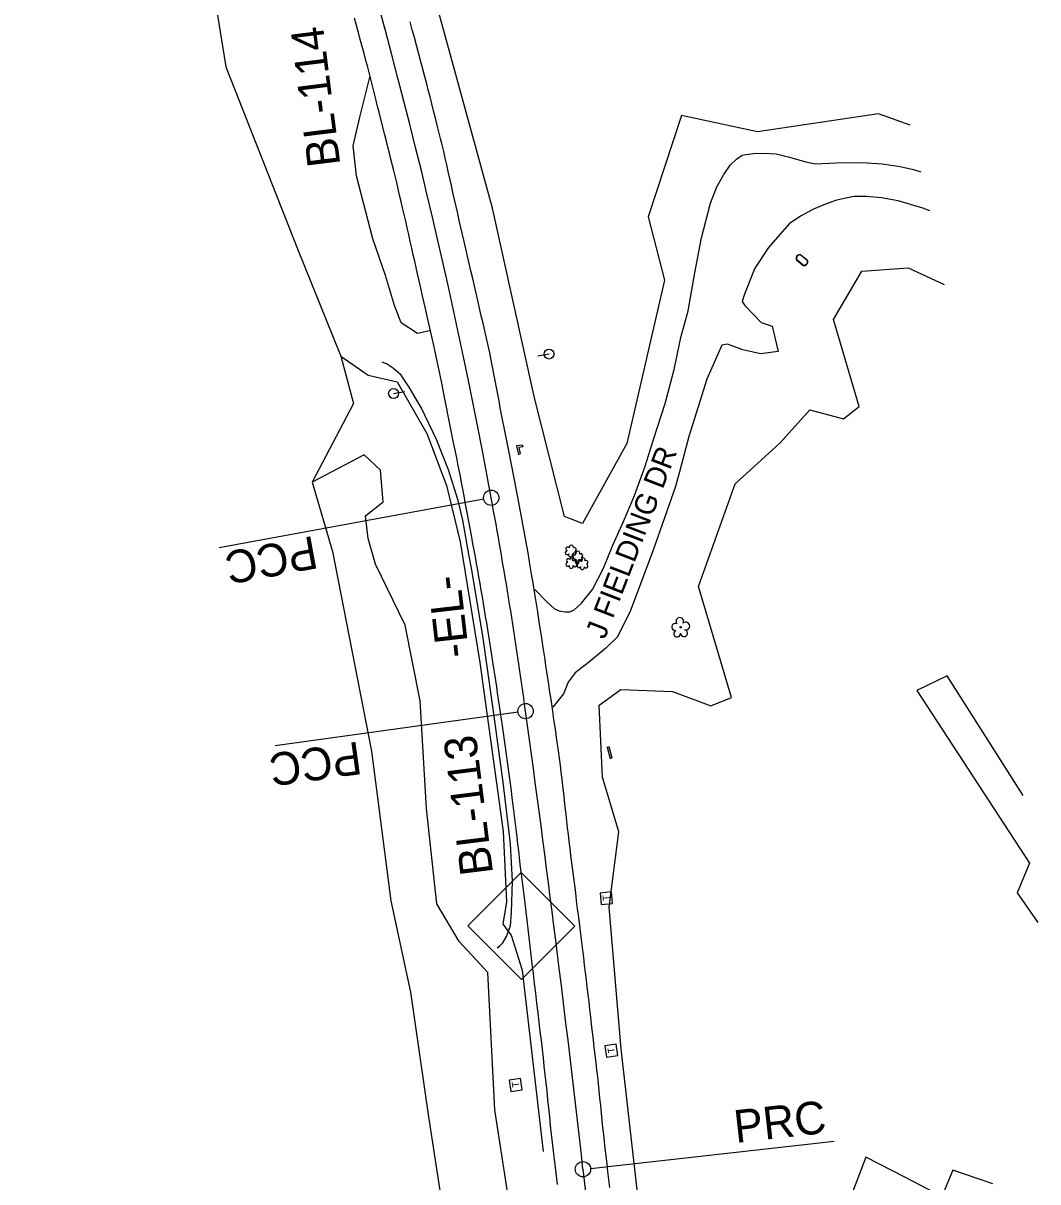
# Model space of a CAD drawing. Extents: x 476627 to 479509, y 495837 to 499842.
# Drawn here: x 477748 to 478245, y 498393 to 498961 of the extents above; entities that cross this region are included whole.
import ezdxf

# ---------------------------------------------------------------- set-up
doc = ezdxf.new("R2010")
doc.units = 0
for name, color, linetype in [('CTL Secondary Horizontal and Vertical CELL', 7, 'Continuous'), ('CTL Secondary Horizontal and Vertical Text', 7, 'Continuous'), ('Exist Guardrail', 7, 'Continuous'), ('Exist Horizontal Alignment', 7, 'Continuous'), ('Exist Horizontal Alignment Direction Label', 7, 'Continuous'), ('Exist Roads EOP', 7, 'Continuous'), ('Exist Roads Soil', 7, 'Continuous'), ('Exist Roads Soil Text', 7, 'Continuous'), ('Exist Structure Minor Head and End Wall', 7, 'Continuous'), ('Exist Utilities Power Pole CELL', 7, 'Continuous'), ('Exist Utilities Telephone Pedestal CELL', 7, 'Continuous'), ('Exist Utilities Water Meter CELL', 7, 'Continuous'), ('Exist Vegetation Hedge Row', 7, 'Continuous'), ('Exist Vegetation Shrub CELL', 7, 'Continuous'), ('Exist Vegetation Tree CELL', 7, 'Continuous'), ('Exist Vegetation Woods Line', 7, 'Continuous')]:
    doc.layers.add(name, color=color, linetype=linetype)

msp = doc.modelspace()

# ---------------------------------------------------------------- linework, layer by layer
at = {"layer": 'CTL Secondary Horizontal and Vertical CELL'}
msp.add_line((477991.73, 498518.4), (477991.73, 498518.4), dxfattribs=at)
msp.add_lwpolyline([(477965.66, 498518.49), (477991.87, 498544.7), (478018.12, 498518.44), (477991.91, 498492.24)], close=True, dxfattribs=at)
at = {"layer": 'Exist Guardrail'}
for points in [[(477966.35, 498699.59), (477963.2, 498717.17), (477960.96, 498726.82), (477956.29, 498741.9), (477950.37, 498756.69), (477942.99, 498772.06), (477937.02, 498782.44), (477933.02, 498788.21), (477929.33, 498791.5), (477925.8, 498793.82), (477923.73, 498794.65)], [(477980.13, 498507.83), (477981.43, 498508.73), (477982.83, 498510.24), (477984.67, 498513.24), (477986.54, 498518.59), (477987.15, 498525.08), (477987.62, 498540.38), (477986.53, 498558.71), (477982.99, 498588.89), (477977.95, 498625.97), (477973.03, 498660.6), (477967.5, 498693.64), (477966.35, 498699.59)]]:
    msp.add_lwpolyline(points, dxfattribs=at)
at = {"layer": 'Exist Horizontal Alignment'}
for p, q in [((477973.47, 498727.54), (477843.87, 498703.69)), ((477990.28, 498623.17), (477871.38, 498606.73)), ((478025.82, 498399.73), (478145.11, 498413.12))]:
    msp.add_line(p, q, dxfattribs=at)
for centre in [(477977.16, 498728.22), (477994, 498623.69), (478022.1, 498399.31)]:
    msp.add_circle(centre, 3.75, dxfattribs=at)
for centre, radius, start, end in [((475150.42, 498208.04), 2874.21, 10.42705, 25.34825), ((475642.7, 498298.63), 2373.66, 7.87106, 10.42705), ((469239.4, 497413.39), 8837.86, 6.405023, 7.871057), ((592937.27, 511299.31), 115636.96, 186.405023, 186.7177067)]:
    msp.add_arc(centre, radius, start, end, dxfattribs=at)
at = {"layer": 'Exist Roads EOP'}
for points in [[(478009.56, 498391.82), (478009.06, 498396.03), (478008.58, 498400.16), (478008.1, 498404.2), (478007.63, 498408.24), (478007.17, 498412.34), (478006.71, 498416.51), (478006.26, 498420.74), (478005.81, 498424.99), (478005.37, 498429.2), (478004.93, 498433.37), (478004.49, 498437.5), (478004.05, 498441.61), (478003.6, 498445.73), (478003.15, 498449.84), (478002.69, 498453.96), (478002.21, 498458.14), (478001.71, 498462.44), (478001.2, 498466.85), (478000.66, 498471.38), (478000.11, 498476), (477999.55, 498480.7), (477998.99, 498485.48), (477998.41, 498490.32), (477997.83, 498495.13), (477997.28, 498499.77), (477996.74, 498504.25), (477996.23, 498508.58), (477995.72, 498512.81), (477995.22, 498517.04), (477994.72, 498521.25), (477994.22, 498525.46), (477993.73, 498529.6), (477993.25, 498533.62), (477992.77, 498537.54), (477992.3, 498541.34), (477991.84, 498545.02), (477991.41, 498548.57), (477991.01, 498551.99), (477990.64, 498555.28), (477990.27, 498558.6), (477989.85, 498562.14), (477989.4, 498565.87), (477988.9, 498569.81), (477988.4, 498573.77), (477987.92, 498577.58), (477987.46, 498581.23), (477987.02, 498584.73), (477986.58, 498588.18), (477986.12, 498591.68), (477985.65, 498595.23), (477985.16, 498598.82), (477984.67, 498602.43), (477984.17, 498605.99), (477983.68, 498609.52), (477983.2, 498613.01), (477982.71, 498616.44), (477982.23, 498619.8), (477981.74, 498623.09), (477981.26, 498626.31), (477980.78, 498629.47), (477980.3, 498632.59), (477979.83, 498635.67), (477979.37, 498638.71), (477978.91, 498641.74), (477978.43, 498644.81), (477977.95, 498647.92), (477977.47, 498651.06), (477976.97, 498654.23), (477976.47, 498657.4), (477975.96, 498660.57), (477975.45, 498663.75), (477974.93, 498666.93), (477974.41, 498670.11), (477973.89, 498673.29), (477973.36, 498676.47), (477972.82, 498679.67), (477972.27, 498682.9), (477971.71, 498686.17), (477971.13, 498689.48), (477970.55, 498692.78), (477969.97, 498696.05), (477969.38, 498699.28), (477968.8, 498702.47), (477968.21, 498705.68), (477967.61, 498708.95), (477966.99, 498712.3), (477966.36, 498715.72), (477965.72, 498719.15), (477965.09, 498722.54), (477964.47, 498725.89), (477963.86, 498729.19), (477963.25, 498732.44), (477962.65, 498735.62), (477962.05, 498738.72), (477961.46, 498741.75), (477960.87, 498744.75), (477960.27, 498747.75), (477959.66, 498750.76), (477959.05, 498753.78), (477958.43, 498756.77), (477957.24, 498762.63), (477956.12, 498768.26), (477955.08, 498773.46), (477954.12, 498778.28), (477953.07, 498783.47), (477951.92, 498789.02), (477950.83, 498794.22), (477949.79, 498799.08), (477948.69, 498804.31), (477947.48, 498809.97), (477946.19, 498815.75), (477944.83, 498821.54), (477943.54, 498827.05), (477942.31, 498832.33), (477941.03, 498837.96), (477940.36, 498840.94), (477939.67, 498844.02), (477938.96, 498847.19), (477938.24, 498850.44), (477937.5, 498853.77), (477936.75, 498857.12), (477936.01, 498860.44), (477935.26, 498863.72), (477934.52, 498866.97), (477933.78, 498870.18), (477933.04, 498873.35), (477932.31, 498876.47), (477931.58, 498879.56), (477930.86, 498882.59), (477929.44, 498888.42), (477928.05, 498894.02), (477927.33, 498896.91), (477926.59, 498899.87), (477925.83, 498902.92), (477925.07, 498905.94), (477923.64, 498911.64), (477922.26, 498916.99), (477921.54, 498919.84), (477920.78, 498922.85), (477919.99, 498926.02), (477919.18, 498929.28), (477918.35, 498932.54), (477917.51, 498935.82), (477916.65, 498939.1), (477915.78, 498942.41), (477914.89, 498945.77), (477913.97, 498949.18), (477913.04, 498952.63), (477912.08, 498956.11), (477911.11, 498959.59), (477910.14, 498963.08)], [(478035.26, 498390.31), (478034.8, 498394.27), (478034.34, 498398.18), (478033.89, 498402.04), (478033.45, 498405.81), (478033.03, 498409.46), (478032.63, 498412.97), (478032.26, 498416.36), (478031.89, 498419.74), (478031.53, 498423.22), (478031.16, 498426.81), (478030.78, 498430.51), (478030.41, 498434.2), (478030.04, 498437.78), (478029.67, 498441.26), (478029.31, 498444.62), (478028.94, 498447.99), (478028.54, 498451.49), (478028.11, 498455.12), (478027.65, 498458.87), (478027.19, 498462.67), (478026.74, 498466.44), (478026.31, 498470.19), (478025.89, 498473.91), (478025.48, 498477.6), (478025.07, 498481.27), (478024.65, 498484.91), (478024.23, 498488.53), (478023.8, 498492.14), (478023.37, 498495.74), (478022.93, 498499.35), (478022.49, 498502.95), (478022.03, 498506.64), (478021.55, 498510.48), (478021.05, 498514.49), (478020.53, 498518.65), (478020, 498522.83), (478019.5, 498526.89), (478019.01, 498530.83), (478018.55, 498534.64), (478018.09, 498538.38), (478017.62, 498542.09), (478017.16, 498545.77), (478016.68, 498549.42), (478016.22, 498553.01), (478015.78, 498556.51), (478015.35, 498559.91), (478014.96, 498563.23), (478014.57, 498566.52), (478014.19, 498569.84), (478013.8, 498573.21), (478013.42, 498576.61), (478013.04, 498580.04), (478012.66, 498583.46), (478012.27, 498586.89), (478011.89, 498590.33), (478011.48, 498593.77), (478011.06, 498597.22), (478010.62, 498600.69), (478010.15, 498604.17), (478009.67, 498607.58), (478009.21, 498610.85), (478008.75, 498613.96), (478007.9, 498619.53), (478007.16, 498624.85), (478006.64, 498628.37), (478005.78, 498633.92), (478005.33, 498636.88), (478004.88, 498639.87), (478004.42, 498642.9), (478003.97, 498645.93), (478003.52, 498648.92), (478002.63, 498654.79), (478001.75, 498660.58), (478000.86, 498666.37), (477999.94, 498672.25), (477999.46, 498675.26), (477998.51, 498681.12), (477997.66, 498686.38), (477996.78, 498691.8), (477996.3, 498694.72), (477995.77, 498697.97), (477995.2, 498701.3), (477994.61, 498704.71), (477993.99, 498708.22), (477993.35, 498711.76), (477992.7, 498715.29), (477992.04, 498718.83), (477991.37, 498722.35), (477990.69, 498725.86), (477990.02, 498729.32), (477989.35, 498732.73), (477988.69, 498736.11), (477988.03, 498739.46), (477987.37, 498742.8), (477986.71, 498746.14), (477986.05, 498749.48), (477985.4, 498752.8), (477984.76, 498756.09), (477984.13, 498759.33), (477983.5, 498762.54), (477982.88, 498765.75), (477982.26, 498769), (477981.62, 498772.29), (477980.98, 498775.61), (477980.34, 498778.95), (477979.71, 498782.28), (477979.09, 498785.6), (477978.48, 498788.91), (477977.84, 498792.26), (477977.15, 498795.67), (477976.42, 498799.15), (477975.63, 498802.7), (477974.81, 498806.31), (477973.99, 498809.96), (477973.15, 498813.64), (477972.31, 498817.37), (477971.47, 498821.09), (477970.62, 498824.78), (477969.78, 498828.44), (477968.93, 498832.06), (477968.08, 498835.67), (477967.23, 498839.28), (477966.38, 498842.89), (477965.52, 498846.51), (477964.67, 498850.1), (477963.85, 498853.64), (477963.05, 498857.13), (477962.27, 498860.57), (477961.5, 498863.99), (477960.73, 498867.4), (477959.96, 498870.83), (477959.2, 498874.25), (477958.43, 498877.67), (477957.67, 498881.09), (477956.91, 498884.51), (477956.15, 498887.93), (477955.39, 498891.31), (477954.64, 498894.61), (477953.88, 498897.85), (477953.11, 498901.01), (477952.34, 498904.17), (477951.53, 498907.42), (477950.7, 498910.76), (477949.83, 498914.19), (477948.95, 498917.65), (477948.07, 498921.12), (477947.19, 498924.59), (477946.31, 498928.06), (477945.42, 498931.55), (477944.5, 498935.1), (477943.56, 498938.7), (477942.59, 498942.35), (477941.59, 498946.06), (477940.58, 498949.81), (477939.54, 498953.6), (477938.48, 498957.45), (477937.41, 498961.34)]]:
    msp.add_lwpolyline(points, dxfattribs=at)
at = {"layer": 'Exist Roads Soil'}
for points in [[(477946.96, 498810.01), (477940.97, 498808.62), (477933.11, 498813.85), (477929.86, 498822.29), (477925.33, 498837), (477919.23, 498854.95), (477911.11, 498885.89), (477909.62, 498900.51), (477912.88, 498914.64), (477917.69, 498934.2)], [(478041.97, 498716.51), (478047.32, 498729.34), (478052.49, 498743.63), (478056.64, 498756.73), (478062.4, 498774.32), (478066.75, 498790.95), (478070.01, 498806.62), (478073.56, 498819.77), (478076.93, 498838.36), (478080.08, 498855.54), (478084.56, 498872.46), (478087.7, 498880.52), (478091.07, 498886.6), (478094.12, 498891.05), (478097.25, 498894.05), (478100.09, 498895.97), (478101.9, 498896.41), (478105.6, 498896.8), (478110.38, 498896.94), (478116.74, 498896.61), (478122.68, 498895.17), (478131.22, 498892.78), (478135.86, 498891.84), (478146.28, 498892.29), (478158.83, 498892.47), (478168.6, 498891.75), (478177.52, 498890.43), (478184, 498889.01), (478187.63, 498887.9)], [(478192, 498868.68), (478188.62, 498869.98), (478176.51, 498873.68), (478168.31, 498875.11), (478160.97, 498875.8), (478154.98, 498875.68), (478150.03, 498874.79), (478145.8, 498873.88), (478140, 498871.6), (478134.77, 498869.38), (478128.71, 498866.06), (478123.16, 498862.38), (478113.02, 498850.7), (478106.2, 498840.61), (478101.18, 498827.95), (478100.11, 498824.41), (478101.42, 498822.29), (478105.39, 498818.19), (478109.32, 498814.08), (478114.84, 498812.2), (478117.63, 498799.76), (478109.13, 498798.68), (478100.46, 498800.61), (478092.87, 498803.38), (478090.11, 498802.9), (478082.8, 498786.24), (478073.98, 498758.22), (478069.43, 498740.96), (478067.38, 498733.66)], [(478067.38, 498733.66), (478056.64, 498702.95), (478045.19, 498672.47), (478038.91, 498659.85), (478033.38, 498654.47), (478024.69, 498647.29), (478018.26, 498642.42), (478014.87, 498637.95), (478012.54, 498632.09), (478007.31, 498625.71)], [(477998.52, 498683.24), (478004.16, 498677.45), (478008.15, 498673.88), (478010.51, 498672.75), (478013.43, 498672.33), (478015.47, 498672.29), (478017.7, 498673.09), (478021.46, 498676.53), (478026.72, 498683.29), (478032.08, 498693.73), (478036.74, 498704.92), (478041.97, 498716.51)]]:
    msp.add_lwpolyline(points, dxfattribs=at)
at = {"layer": 'Exist Structure Minor Head and End Wall'}
for p, q in [((477992.49, 498754.01), (477992.61, 498753.19)), ((477990.57, 498749.46), (477991.38, 498749.65)), ((478034.03, 498606.1), (478034.84, 498606.3)), ((478034.03, 498606.1), (478035.4, 498600.57)), ((478034.84, 498606.3), (478036.21, 498600.77)), ((478035.4, 498600.57), (478036.21, 498600.77))]:
    msp.add_line(p, q, dxfattribs=at)
for points in [[(477992.49, 498754.01), (477989.59, 498753.59), (477990.57, 498749.46)], [(477992.61, 498753.19), (477990.61, 498752.9), (477991.38, 498749.65)]]:
    msp.add_lwpolyline(points, dxfattribs=at)
at = {"layer": 'Exist Utilities Power Pole CELL'}
for p, q in [((478005.47, 498798.61), (477999.94, 498797.58)), ((478005.47, 498798.61), (478005.47, 498798.61)), ((477929.35, 498779.23), (477934.89, 498780.19)), ((477929.35, 498779.23), (477929.35, 498779.23))]:
    msp.add_line(p, q, dxfattribs=at)
for centre in [(478005.47, 498798.61), (477929.35, 498779.23)]:
    msp.add_circle(centre, 2.45, dxfattribs=at)
at = {"layer": 'Exist Utilities Telephone Pedestal CELL'}
for p, q in [((478033.49, 498531.98), (478033.49, 498531.98)), ((478036.03, 498457.28), (478036.03, 498457.28)), ((477989.1, 498440.53), (477989.1, 498440.53))]:
    msp.add_line(p, q, dxfattribs=at)
for points in [[(478036.57, 498529.54), (478036.03, 498535.11), (478030.46, 498534.57), (478031, 498529), (478036.57, 498529.54)], [(478039.22, 498455), (478038.4, 498460.53), (478032.86, 498459.71), (478033.69, 498454.17), (478039.22, 498455)], [(477992.26, 498438.21), (477991.52, 498443.75), (477985.97, 498443.01), (477986.71, 498437.47), (477992.26, 498438.21)]]:
    msp.add_lwpolyline(points, dxfattribs=at)
at = {"layer": 'Exist Utilities Water Meter CELL'}
msp.add_line((478129.35, 498844.62), (478129.35, 498844.62), dxfattribs=at)
for points in [[(478128.76, 498847.12), (478131.93, 498844.52)], [(478128.85, 498847.23), (478132.02, 498844.63)], [(478129.85, 498842.02), (478126.7, 498844.6)], [(478129.93, 498842.12), (478126.78, 498844.71)]]:
    msp.add_lwpolyline(points, dxfattribs=at)
for centre, radius, start, end in [((478128.35, 498845.44), 1.86, 74.3025, 206.9626), ((478128.34, 498845.45), 1.73, 75.7814, 205.527), ((478130.36, 498843.8), 1.86, 253.8322, 26.6336), ((478130.35, 498843.81), 1.73, 255.9551, 24.4366)]:
    msp.add_arc(centre, radius, start, end, dxfattribs=at)
at = {"layer": 'Exist Vegetation Hedge Row'}
for points in [[(477903.45, 498797.63), (477916.96, 498788.32), (477931.12, 498784.97), (477945.58, 498759.61), (477955.28, 498734.27), (477961.94, 498706.58)], [(477916.85, 498708.28), (477915.5, 498719.35), (477924.23, 498726.13), (477923, 498741.71), (477914.94, 498749.31), (477889.45, 498735.82)], [(477963.92, 498311.35), (477977.85, 498311.67), (477991.77, 498320.81), (477996.36, 498327.92), (477987.9, 498370.28), (477978.86, 498428.47), (477975.53, 498495.68), (477961.52, 498510.8), (477950.56, 498529.32), (477945.43, 498576.07), (477942.36, 498628.75), (477934.97, 498665.8), (477920.5, 498695.73), (477916.85, 498708.28)], [(477961.94, 498706.58), (477971.52, 498647.49), (477982.99, 498564.73), (477984.62, 498530.33), (477982.85, 498519.27), (477986.87, 498514.03), (477992.36, 498496.75), (478002.54, 498408.07)]]:
    msp.add_lwpolyline(points, dxfattribs=at)
at = {"layer": 'Exist Vegetation Shrub CELL'}
for p, q in [((478016.18, 498701.98), (478016.18, 498701.98)), ((478016.48, 498696.29), (478016.48, 498696.29)), ((478019.37, 498699.01), (478019.37, 498699.01)), ((478021.93, 498695.69), (478021.93, 498695.69))]:
    msp.add_line(p, q, dxfattribs=at)
for centre, radius, start, end in [((478016.4, 498704.02), 0.99, 334.8391, 200.4717), ((478014.37, 498701.27), 0.955, 95.1099, 327.9534), ((478014.69, 498703.1), 0.968, 35.8908, 245.4216), ((478016.05, 498700.29), 0.984, 151.2797, 21.387), ((478016.71, 498698.33), 0.99, 334.8391, 200.4717), ((478017.89, 498700.14), 0.968, 35.8908, 245.4216), ((478017.81, 498701.05), 0.937, 204.9913, 73.4601), ((478017.85, 498702.85), 0.929, 284.4567, 126.0861), ((478019.6, 498701.05), 0.99, 334.8391, 200.4717), ((478021.04, 498699.88), 0.929, 284.4567, 126.0861), ((478014.68, 498695.59), 0.955, 95.1099, 327.9534), ((478015, 498697.42), 0.968, 35.8908, 245.4216), ((478016.36, 498694.61), 0.984, 151.2797, 21.387), ((478017.57, 498698.3), 0.955, 95.1099, 327.9534), ((478018.12, 498695.36), 0.937, 204.9913, 73.4601), ((478018.16, 498697.16), 0.929, 284.4567, 126.0861), ((478019.24, 498697.33), 0.984, 151.2797, 21.387), ((478020.13, 498694.99), 0.955, 95.1099, 327.9534), ((478020.45, 498696.82), 0.968, 35.8908, 245.4216), ((478021.01, 498698.08), 0.937, 204.9913, 73.4601), ((478021.8, 498694.01), 0.984, 151.2797, 21.387), ((478022.16, 498697.73), 0.99, 334.8391, 200.4717), ((478023.57, 498694.76), 0.937, 204.9913, 73.4601), ((478023.6, 498696.56), 0.929, 284.4567, 126.0861)]:
    msp.add_arc(centre, radius, start, end, dxfattribs=at)
at = {"layer": 'Exist Vegetation Tree CELL'}
msp.add_line((478069.93, 498664.79), (478069.93, 498664.79), dxfattribs=at)
msp.add_circle((478069.93, 498664.79), 0.326, dxfattribs=at)
for centre, radius, start, end in [((478067.33, 498664.94), 1.73, 62.6636, 279.3457), ((478069.55, 498667.66), 1.86, 330.1651, 219.7134), ((478072.48, 498665.38), 1.9, 257.1011, 134.1999), ((478068.23, 498661.67), 1.69, 111.5671, 6.231), ((478071.61, 498661.89), 1.7, 181.2822, 74.56)]:
    msp.add_arc(centre, radius, start, end, dxfattribs=at)
at = {"layer": 'Exist Vegetation Woods Line'}
for points in [[(478182.3, 498910.77), (478166.83, 498916.31), (478107.63, 498907.49), (478070.29, 498915.49), (478054.1, 498865.86), (478062.04, 498834.83), (478043.51, 498754.74), (478021.79, 498715.6), (478012.98, 498719.06), (477998.42, 498777.13), (477977.8, 498870.01), (477942.42, 498999.34), (477929.03, 499039.05), (477877.26, 499206.51)], [(477771.36, 499171.02), (477801.04, 499098.02), (477836.35, 499006.26), (477847.24, 498939.21), (477882.23, 498850.13), (477903.45, 498797.63), (477909.74, 498774.45), (477889.45, 498735.82), (477899.46, 498701.89)], [(478096.71, 498735.02), (478118.76, 498755.05), (478133.15, 498771.21), (478149.79, 498766.93), (478157.42, 498772.89), (478144.82, 498815.57), (478158.68, 498839.22), (478181.38, 498840.88), (478198.96, 498832.66)], [(478071.03, 498217.47), (478056.11, 498323.15), (478040.82, 498458.32), (478034.94, 498527.74), (478039.59, 498564.51), (478031.67, 498591.42), (478030.01, 498626.63), (478040.61, 498634.33), (478065.91, 498633.36), (478084.75, 498626.27), (478094.83, 498630.37), (478078.73, 498684.72), (478096.71, 498735.02)], [(477899.46, 498701.89), (477918.46, 498604.12), (477927.94, 498530.85), (477937.69, 498486.12), (477946.46, 498424.92), (477963.92, 498311.35), (477964.48, 498292.29), (477968.75, 498259.54), (477979.45, 498191.25)], [(478237.72, 498582.31), (478200.43, 498640.96), (478185.59, 498633.76), (478240.75, 498549.26), (478234.74, 498534.67), (478244.89, 498520.18)], [(478222.86, 498392.1), (478203.2, 498398.8), (478197.95, 498385.96), (478180.07, 498395.32), (478160.69, 498405.23), (478154.13, 498388.02)]]:
    msp.add_lwpolyline(points, dxfattribs=at)

# ---------------------------------------------------------------- texts
at = {"layer": 'CTL Secondary Horizontal and Vertical Text'}
for s, p in [('BL-114', (477903.3, 498891.23)), ('BL-113', (477978.11, 498544.23))]:
    msp.add_text(s, height=16, rotation=97.1248, dxfattribs=at).set_placement(p)
at = {"layer": 'Exist Horizontal Alignment'}
for s, rotation, p in [('PCC', 190.4271, (477890.26, 498709.62)), ('PCC', 187.8711, (477912.37, 498608.85)), ('PRC', 6.405, (478096.95, 498412.15))]:
    msp.add_text(s, height=16, rotation=rotation, dxfattribs=at).set_placement(p)
at = {"layer": 'Exist Horizontal Alignment Direction Label'}
msp.add_text('-EL-', height=16, rotation=96.5685, dxfattribs=at).set_placement((477966.42, 498650.63))
at = {"layer": 'Exist Roads Soil Text'}
msp.add_text('J FIELDING DR ', height=10.4, rotation=68.9221, dxfattribs=at).set_placement((478032.77, 498658.47))
at = {"layer": 'Exist Utilities Telephone Pedestal CELL'}
for rotation, p in [(95.5123, (478035.31, 498531.02)), (98.499, (478037.89, 498456.41)), (97.5724, (477990.94, 498439.64))]:
    msp.add_text('T', height=3.42, rotation=rotation, dxfattribs=at).set_placement(p)

doc.saveas('drawing.dxf')
